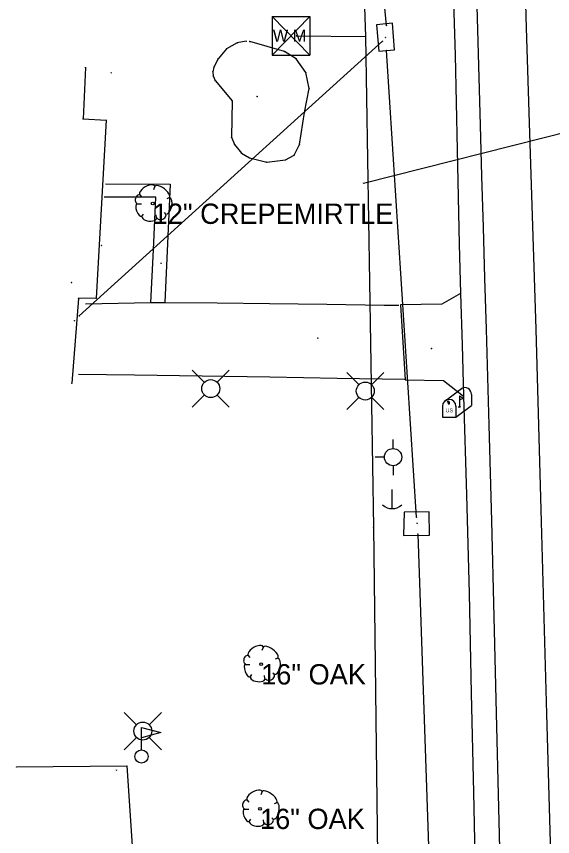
# Model space of a CAD drawing. Extents: x 1930288 to 1941089, y 588389 to 611475.
# Drawn here: x 1930752.1 to 1930884, y 597803.8 to 598005.7 of the extents above; entities that cross this region are included whole.
import ezdxf

# ---------------------------------------------------------------- set-up
doc = ezdxf.new("R2010")
doc.units = 0
for name, color, linetype in [('S_BUILDING', 7, 'Continuous'), ('S_DRG_PT_SYM', 7, 'Continuous'), ('S_DRIVEWAY', 7, 'Continuous'), ('S_DROP_INLET', 7, 'Continuous'), ('S_EDGE_PAVEMENT', 7, 'Continuous'), ('S_FLAG_POLE', 7, 'Continuous'), ('S_GRD_PT_SYM', 7, 'Continuous'), ('S_LANDSCAPING', 7, 'Continuous'), ('S_MAILBOX', 7, 'Continuous'), ('S_MSC_PT_SYM', 7, 'Continuous'), ('S_PAVEMENT_CROWN', 7, 'Continuous'), ('S_SANITARY_SEWER', 7, 'Continuous'), ('S_SHOULDER', 7, 'Continuous'), ('S_SIDEWALK', 7, 'Continuous'), ('S_STORM_SEWER', 7, 'Continuous'), ('S_STR_PT_SYM', 7, 'Continuous'), ('S_TREE', 7, 'Continuous'), ('S_TREE_ANNOT', 7, 'Continuous'), ('S_UTILITY_POLE', 7, 'Continuous'), ('S_UTL_PT_SYM', 7, 'Continuous'), ('S_WATER_UTILITIES', 7, 'Continuous')]:
    doc.layers.add(name, color=color, linetype=linetype)

msp = doc.modelspace()

# ---------------------------------------------------------------- linework, layer by layer
at = {"layer": 'S_BUILDING'}
for p, q in [((1930769.15, 597993.1), (1930768.55, 597980.46)), ((1930768.55, 597980.46), (1930774.22, 597980.17)), ((1930774.22, 597980.17), (1930771.74, 597936.32)), ((1930767.36, 597936.21), (1930765.74, 597915.38)), ((1930771.74, 597936.32), (1930767.36, 597936.21)), ((1930752.17, 597820.91), (1930779.32, 597821.17)), ((1930779.32, 597821.17), (1930780.88, 597796.72))]:
    msp.add_line(p, q, dxfattribs=at)
at = {"layer": 'S_DRG_PT_SYM'}
for points in [[(1930842.89, 598000.52), (1930842.89, 598000.57), (1930842.89, 598000.52), (1930842.84, 598000.52), (1930842.89, 598000.52), (1930842.89, 598000.47), (1930842.89, 598000.52), (1930842.94, 598000.52)], [(1930766.4, 597930.76), (1930766.4, 597930.81), (1930766.4, 597930.76), (1930766.35, 597930.76), (1930766.4, 597930.76), (1930766.4, 597930.71), (1930766.4, 597930.76), (1930766.45, 597930.76)], [(1930850.71, 597880.91), (1930850.71, 597880.96), (1930850.71, 597880.91), (1930850.66, 597880.91), (1930850.71, 597880.91), (1930850.71, 597880.86), (1930850.71, 597880.91), (1930850.76, 597880.91)]]:
    msp.add_lwpolyline(points, dxfattribs=at)
at = {"layer": 'S_DRIVEWAY'}
for points in [[(1930861.39, 597937.48), (1930856.83, 597934.8), (1930846.65, 597934.64), (1930847.76, 597916.23), (1930857.19, 597916.08), (1930862.15, 597912.21)], [(1930769.09, 597934.89), (1930785.23, 597935.26), (1930788.63, 597935.25), (1930801.52, 597935.14), (1930814.41, 597935.02), (1930828.49, 597934.8), (1930842.58, 597934.58), (1930846.18, 597934.58)], [(1930847.61, 597916.26), (1930831.06, 597916.56), (1930814.5, 597916.86), (1930797.85, 597917.11), (1930781.19, 597917.37), (1930767.38, 597917.52)]]:
    msp.add_lwpolyline(points, dxfattribs=at)
at = {"layer": 'S_DROP_INLET'}
for points in [[(1930840.69, 598003.64), (1930841.3, 597997.15), (1930845.17, 597997.43), (1930844.65, 598003.98)], [(1930844.65, 598003.98), (1930840.69, 598003.64)], [(1930847.51, 597883.66), (1930847.36, 597877.87), (1930853.74, 597877.95), (1930853.7, 597883.75)], [(1930853.7, 597883.75), (1930847.51, 597883.66)]]:
    msp.add_lwpolyline(points, dxfattribs=at)
at = {"layer": 'S_EDGE_PAVEMENT'}
msp.add_lwpolyline([(1930861.97, 598136.6), (1930862.32, 598122.16), (1930862.67, 598107.72), (1930863.02, 598093.28), (1930863.37, 598078.84), (1930863.8, 598061.3), (1930864.24, 598043.75), (1930864.93, 598025.92), (1930865.59, 598002.39), (1930866.24, 597978.87), (1930866.59, 597966.32), (1930866.95, 597953.76), (1930867.3, 597941.21), (1930867.66, 597928.66), (1930868.33, 597905.09), (1930869.01, 597881.53), (1930869.59, 597857.83), (1930870.18, 597834.13), (1930870.73, 597810.89), (1930871.29, 597787.65)], dxfattribs=at)
at = {"layer": 'S_FLAG_POLE'}
for p, q in [((1930782.9, 597825.12), (1930782.9, 597830.66)), ((1930782.9, 597830.66), (1930787.67, 597829.38)), ((1930787.67, 597829.38), (1930782.9, 597828.1))]:
    msp.add_line(p, q, dxfattribs=at)
msp.add_circle((1930782.9, 597823.49), 1.63, dxfattribs=at)
at = {"layer": 'S_GRD_PT_SYM'}
for points in [[(1930806.46, 597999.14), (1930806.46, 597999.19), (1930806.46, 597999.14), (1930806.41, 597999.14), (1930806.46, 597999.14), (1930806.46, 597999.09), (1930806.46, 597999.14), (1930806.51, 597999.14)], [(1930808.66, 597999.57), (1930808.66, 597999.62), (1930808.66, 597999.57), (1930808.61, 597999.57), (1930808.66, 597999.57), (1930808.66, 597999.52), (1930808.66, 597999.57), (1930808.71, 597999.57)], [(1930809.55, 597999.5), (1930809.55, 597999.55), (1930809.55, 597999.5), (1930809.5, 597999.5), (1930809.55, 597999.5), (1930809.55, 597999.45), (1930809.55, 597999.5), (1930809.6, 597999.5)], [(1930803.79, 597997.67), (1930803.79, 597997.72), (1930803.79, 597997.67), (1930803.74, 597997.67), (1930803.79, 597997.67), (1930803.79, 597997.62), (1930803.79, 597997.67), (1930803.84, 597997.67)], [(1930801.75, 597995.24), (1930801.75, 597995.29), (1930801.75, 597995.24), (1930801.7, 597995.24), (1930801.75, 597995.24), (1930801.75, 597995.19), (1930801.75, 597995.24), (1930801.8, 597995.24)], [(1930818.07, 597997.02), (1930818.07, 597997.07), (1930818.07, 597997.02), (1930818.02, 597997.02), (1930818.07, 597997.02), (1930818.07, 597996.97), (1930818.07, 597997.02), (1930818.12, 597997.02)], [(1930820.93, 597995.25), (1930820.93, 597995.3), (1930820.93, 597995.25), (1930820.88, 597995.25), (1930820.93, 597995.25), (1930820.93, 597995.2), (1930820.93, 597995.25), (1930820.98, 597995.25)], [(1930800.71, 597993.22), (1930800.71, 597993.27), (1930800.71, 597993.22), (1930800.66, 597993.22), (1930800.71, 597993.22), (1930800.71, 597993.17), (1930800.71, 597993.22), (1930800.76, 597993.22)], [(1930800.46, 597992.05), (1930800.46, 597992.1), (1930800.46, 597992.05), (1930800.41, 597992.05), (1930800.46, 597992.05), (1930800.46, 597992), (1930800.46, 597992.05), (1930800.51, 597992.05)], [(1930823.3, 597991.91), (1930823.3, 597991.96), (1930823.3, 597991.91), (1930823.25, 597991.91), (1930823.3, 597991.91), (1930823.3, 597991.86), (1930823.3, 597991.91), (1930823.35, 597991.91)], [(1930800.57, 597991.01), (1930800.57, 597991.06), (1930800.57, 597991.01), (1930800.52, 597991.01), (1930800.57, 597991.01), (1930800.57, 597990.96), (1930800.57, 597991.01), (1930800.62, 597991.01)], [(1930800.99, 597989.87), (1930800.99, 597989.92), (1930800.99, 597989.87), (1930800.94, 597989.87), (1930800.99, 597989.87), (1930800.99, 597989.82), (1930800.99, 597989.87), (1930801.04, 597989.87)], [(1930824.11, 597987.91), (1930824.11, 597987.96), (1930824.11, 597987.91), (1930824.06, 597987.91), (1930824.11, 597987.91), (1930824.11, 597987.86), (1930824.11, 597987.91), (1930824.16, 597987.91)], [(1930805.22, 597984.88), (1930805.22, 597984.93), (1930805.22, 597984.88), (1930805.17, 597984.88), (1930805.22, 597984.88), (1930805.22, 597984.83), (1930805.22, 597984.88), (1930805.27, 597984.88)], [(1930823.01, 597982.05), (1930823.01, 597982.1), (1930823.01, 597982.05), (1930822.96, 597982.05), (1930823.01, 597982.05), (1930823.01, 597982), (1930823.01, 597982.05), (1930823.06, 597982.05)], [(1930805.08, 597975.91), (1930805.08, 597975.96), (1930805.08, 597975.91), (1930805.03, 597975.91), (1930805.08, 597975.91), (1930805.08, 597975.86), (1930805.08, 597975.91), (1930805.13, 597975.91)], [(1930805.77, 597974.17), (1930805.77, 597974.22), (1930805.77, 597974.17), (1930805.72, 597974.17), (1930805.77, 597974.17), (1930805.77, 597974.12), (1930805.77, 597974.17), (1930805.82, 597974.17)], [(1930821.81, 597974.17), (1930821.81, 597974.22), (1930821.81, 597974.17), (1930821.76, 597974.17), (1930821.81, 597974.17), (1930821.81, 597974.12), (1930821.81, 597974.17), (1930821.86, 597974.17)], [(1930807.54, 597971.99), (1930807.54, 597972.04), (1930807.54, 597971.99), (1930807.49, 597971.99), (1930807.54, 597971.99), (1930807.54, 597971.94), (1930807.54, 597971.99), (1930807.59, 597971.99)], [(1930809.49, 597970.89), (1930809.49, 597970.94), (1930809.49, 597970.89), (1930809.44, 597970.89), (1930809.49, 597970.89), (1930809.49, 597970.84), (1930809.49, 597970.89), (1930809.54, 597970.89)], [(1930820.45, 597971.55), (1930820.45, 597971.6), (1930820.45, 597971.55), (1930820.4, 597971.55), (1930820.45, 597971.55), (1930820.45, 597971.5), (1930820.45, 597971.55), (1930820.5, 597971.55)], [(1930813.73, 597969.81), (1930813.73, 597969.86), (1930813.73, 597969.81), (1930813.68, 597969.81), (1930813.73, 597969.81), (1930813.73, 597969.76), (1930813.73, 597969.81), (1930813.78, 597969.81)], [(1930818.34, 597970.34), (1930818.34, 597970.39), (1930818.34, 597970.34), (1930818.29, 597970.34), (1930818.34, 597970.34), (1930818.34, 597970.29), (1930818.34, 597970.34), (1930818.39, 597970.34)]]:
    msp.add_lwpolyline(points, dxfattribs=at)
at = {"layer": 'S_LANDSCAPING'}
for p, q in [((1930806.46, 597999.14), (1930803.79, 597997.67)), ((1930808.66, 597999.57), (1930806.46, 597999.14)), ((1930818.07, 597997.02), (1930809.55, 597999.5)), ((1930803.79, 597997.67), (1930801.75, 597995.24)), ((1930801.75, 597995.24), (1930800.71, 597993.22)), ((1930820.93, 597995.25), (1930818.07, 597997.02)), ((1930823.3, 597991.91), (1930820.93, 597995.25)), ((1930800.71, 597993.22), (1930800.46, 597992.05)), ((1930800.46, 597992.05), (1930800.57, 597991.01)), ((1930824.11, 597987.91), (1930823.3, 597991.91)), ((1930800.57, 597991.01), (1930800.99, 597989.87)), ((1930800.99, 597989.87), (1930805.22, 597984.88)), ((1930823.01, 597982.05), (1930824.11, 597987.91)), ((1930805.22, 597984.88), (1930805.08, 597975.91)), ((1930821.81, 597974.17), (1930823.01, 597982.05)), ((1930805.08, 597975.91), (1930805.77, 597974.17)), ((1930805.77, 597974.17), (1930807.54, 597971.99)), ((1930820.45, 597971.55), (1930821.81, 597974.17)), ((1930807.54, 597971.99), (1930809.49, 597970.89)), ((1930809.49, 597970.89), (1930813.73, 597969.81)), ((1930818.34, 597970.34), (1930820.45, 597971.55)), ((1930813.73, 597969.81), (1930818.34, 597970.34))]:
    msp.add_line(p, q, dxfattribs=at)
at = {"layer": 'S_MAILBOX'}
for p, q in [((1930857.49, 597911), (1930861.62, 597914.11)), ((1930864.06, 597912.64), (1930864.06, 597909.92)), ((1930861.11, 597912.29), (1930861.11, 597909.58)), ((1930856.94, 597909.73), (1930856.94, 597907.01)), ((1930860.26, 597907.01), (1930864.06, 597909.92)), ((1930860.26, 597909.73), (1930860.26, 597907.01)), ((1930856.94, 597907.01), (1930860.26, 597907.01))]:
    msp.add_line(p, q, dxfattribs=at)
for points in [[(1930858.12, 597910.84), (1930858.34, 597910.71), (1930858.34, 597910.32), (1930858.65, 597910.32), (1930858.65, 597910.68), (1930858.45, 597910.93), (1930858.12, 597910.87)], [(1930861.11, 597912.29), (1930862.21, 597911.63), (1930861.11, 597911.28)]]:
    msp.add_lwpolyline(points, dxfattribs=at)
for centre, end in [((1930862.39, 597912.64), 117.5718), ((1930858.6, 597909.73), 180)]:
    msp.add_arc(centre, 1.66, 0, end, dxfattribs=at)
msp.add_ellipse((1930861.11, 597909.58), major_axis=(0.145, 0.132), ratio=0.564646, dxfattribs=at)
at = {"layer": 'S_MSC_PT_SYM'}
for points in [[(1930843.2, 598003.4), (1930843.2, 598003.45), (1930843.2, 598003.4), (1930843.15, 598003.4), (1930843.2, 598003.4), (1930843.2, 598003.35), (1930843.2, 598003.4), (1930843.25, 598003.4)], [(1930842.16, 597999.56), (1930842.16, 597999.61), (1930842.16, 597999.56), (1930842.1, 597999.56), (1930842.16, 597999.56), (1930842.16, 597999.51), (1930842.16, 597999.56), (1930842.21, 597999.56)], [(1930843.15, 597997.3), (1930843.15, 597997.35), (1930843.15, 597997.3), (1930843.1, 597997.3), (1930843.15, 597997.3), (1930843.15, 597997.25), (1930843.15, 597997.3), (1930843.2, 597997.3)], [(1930775.45, 597991.8), (1930775.45, 597991.85), (1930775.45, 597991.8), (1930775.4, 597991.8), (1930775.45, 597991.8), (1930775.45, 597991.75), (1930775.45, 597991.8), (1930775.5, 597991.8)], [(1930811.36, 597985.96), (1930811.36, 597986.01), (1930811.36, 597985.96), (1930811.31, 597985.96), (1930811.36, 597985.96), (1930811.36, 597985.91), (1930811.36, 597985.96), (1930811.41, 597985.96)], [(1930773.03, 597949.32), (1930773.03, 597949.37), (1930773.03, 597949.32), (1930772.98, 597949.32), (1930773.03, 597949.32), (1930773.03, 597949.27), (1930773.03, 597949.32), (1930773.08, 597949.32)], [(1930787.72, 597944.92), (1930787.72, 597944.97), (1930787.72, 597944.92), (1930787.67, 597944.92), (1930787.72, 597944.92), (1930787.72, 597944.87), (1930787.72, 597944.92), (1930787.77, 597944.92)], [(1930765.68, 597940.16), (1930765.68, 597940.21), (1930765.68, 597940.16), (1930765.63, 597940.16), (1930765.68, 597940.16), (1930765.68, 597940.11), (1930765.68, 597940.16), (1930765.73, 597940.16)], [(1930767.59, 597931.96), (1930767.59, 597932.01), (1930767.59, 597931.96), (1930767.54, 597931.96), (1930767.59, 597931.96), (1930767.59, 597931.91), (1930767.59, 597931.96), (1930767.64, 597931.96)], [(1930826.28, 597926.51), (1930826.28, 597926.56), (1930826.28, 597926.51), (1930826.23, 597926.51), (1930826.28, 597926.51), (1930826.28, 597926.46), (1930826.28, 597926.51), (1930826.33, 597926.51)], [(1930854.24, 597923.93), (1930854.24, 597923.98), (1930854.24, 597923.93), (1930854.19, 597923.93), (1930854.24, 597923.93), (1930854.24, 597923.88), (1930854.24, 597923.93), (1930854.29, 597923.93)], [(1930850.52, 597882.37), (1930850.52, 597882.42), (1930850.52, 597882.37), (1930850.47, 597882.37), (1930850.52, 597882.37), (1930850.52, 597882.32), (1930850.52, 597882.37), (1930850.57, 597882.37)], [(1930850.87, 597878.26), (1930850.87, 597878.31), (1930850.87, 597878.26), (1930850.82, 597878.26), (1930850.87, 597878.26), (1930850.87, 597878.21), (1930850.87, 597878.26), (1930850.92, 597878.26)], [(1930776.77, 597820.14), (1930776.77, 597820.19), (1930776.77, 597820.14), (1930776.72, 597820.14), (1930776.77, 597820.14), (1930776.77, 597820.09), (1930776.77, 597820.14), (1930776.82, 597820.14)]]:
    msp.add_lwpolyline(points, dxfattribs=at)
at = {"layer": 'S_PAVEMENT_CROWN'}
msp.add_lwpolyline([(1930874.52, 598135.93), (1930874.85, 598121.34), (1930875.18, 598106.75), (1930875.51, 598092.15), (1930875.84, 598077.56), (1930876.1, 598064.74), (1930876.35, 598051.91), (1930876.61, 598039.09), (1930876.86, 598026.27), (1930877.56, 598002.85), (1930878.25, 597979.44), (1930878.66, 597966.75), (1930879.07, 597954.07), (1930879.48, 597941.38), (1930879.89, 597928.7), (1930880.57, 597904.97), (1930881.24, 597881.25), (1930881.88, 597857.6), (1930882.52, 597833.95), (1930883.18, 597810.9), (1930883.85, 597787.85)], dxfattribs=at)
at = {"layer": 'S_SANITARY_SEWER'}
msp.add_line((1930837.54, 597964.65), (1930896.27, 597979.53), dxfattribs=at)
at = {"layer": 'S_SHOULDER'}
msp.add_lwpolyline([(1930861.97, 598136.6), (1930856.85, 598136.29), (1930857.08, 598121.84), (1930857.31, 598107.38), (1930857.54, 598092.92), (1930857.77, 598078.47), (1930858.08, 598061.18), (1930858.39, 598043.88), (1930859.23, 598022.21), (1930859.65, 598009.16), (1930860.08, 597996.1), (1930860.58, 597972.84), (1930861.09, 597949.57), (1930861.39, 597937.48), (1930861.77, 597924.84), (1930862.15, 597912.21), (1930862.82, 597887.9), (1930863.5, 597863.59), (1930864.03, 597839.11), (1930864.57, 597814.62), (1930865.11, 597791.12)], dxfattribs=at)
at = {"layer": 'S_SIDEWALK'}
for points in [[(1930774.01, 597964.5), (1930789.91, 597964.38), (1930789.27, 597949.81), (1930788.63, 597935.25)], [(1930785.23, 597935.26), (1930785.83, 597948.2), (1930786.43, 597961.14), (1930773.7, 597961.19)]]:
    msp.add_lwpolyline(points, dxfattribs=at)
at = {"layer": 'S_STORM_SEWER'}
for p, q in [((1930843.2, 598003.4), (1930828.55, 598152.44)), ((1930842.16, 597999.56), (1930767.59, 597931.96)), ((1930850.52, 597882.37), (1930843.15, 597997.3)), ((1930850.87, 597878.26), (1930854.28, 597778.44))]:
    msp.add_line(p, q, dxfattribs=at)
at = {"layer": 'S_STR_PT_SYM'}
for points in [[(1930769.15, 597993.1), (1930769.15, 597993.15), (1930769.15, 597993.1), (1930769.1, 597993.1), (1930769.15, 597993.1), (1930769.15, 597993.05), (1930769.15, 597993.1), (1930769.2, 597993.1)], [(1930768.55, 597980.46), (1930768.55, 597980.51), (1930768.55, 597980.46), (1930768.5, 597980.46), (1930768.55, 597980.46), (1930768.55, 597980.41), (1930768.55, 597980.46), (1930768.6, 597980.46)], [(1930774.22, 597980.17), (1930774.22, 597980.22), (1930774.22, 597980.17), (1930774.17, 597980.17), (1930774.22, 597980.17), (1930774.22, 597980.12), (1930774.22, 597980.17), (1930774.27, 597980.17)], [(1930767.36, 597936.21), (1930767.36, 597936.26), (1930767.36, 597936.21), (1930767.31, 597936.21), (1930767.36, 597936.21), (1930767.36, 597936.16), (1930767.36, 597936.21), (1930767.41, 597936.21)], [(1930771.74, 597936.32), (1930771.74, 597936.37), (1930771.74, 597936.32), (1930771.69, 597936.32), (1930771.74, 597936.32), (1930771.74, 597936.27), (1930771.74, 597936.32), (1930771.79, 597936.32)], [(1930765.74, 597915.38), (1930765.74, 597915.43), (1930765.74, 597915.38), (1930765.69, 597915.38), (1930765.74, 597915.38), (1930765.74, 597915.33), (1930765.74, 597915.38), (1930765.79, 597915.38)], [(1930752.17, 597820.91), (1930752.17, 597820.96), (1930752.17, 597820.91), (1930752.12, 597820.91), (1930752.17, 597820.91), (1930752.17, 597820.86), (1930752.17, 597820.91), (1930752.22, 597820.91)], [(1930779.32, 597821.17), (1930779.32, 597821.22), (1930779.32, 597821.17), (1930779.27, 597821.17), (1930779.32, 597821.17), (1930779.32, 597821.12), (1930779.32, 597821.17), (1930779.37, 597821.17)]]:
    msp.add_lwpolyline(points, dxfattribs=at)
at = {"layer": 'S_TREE'}
for p, q in [((1930786.21, 597963.85), (1930785.82, 597963)), ((1930782.41, 597961.83), (1930782.91, 597961.25)), ((1930789.77, 597961.06), (1930789.11, 597960.79)), ((1930781.75, 597959.51), (1930782.87, 597959.51)), ((1930782.91, 597956.33), (1930783.38, 597957.03)), ((1930786.59, 597956.06), (1930786.52, 597956.84)), ((1930789, 597956.95), (1930788.53, 597957.38)), ((1930812.89, 597850.47), (1930812.5, 597849.62)), ((1930809.09, 597848.45), (1930809.59, 597847.87)), ((1930808.43, 597846.13), (1930809.55, 597846.13)), ((1930816.45, 597847.68), (1930815.79, 597847.41)), ((1930815.68, 597843.57), (1930815.21, 597844)), ((1930809.59, 597842.95), (1930810.06, 597843.65)), ((1930813.27, 597842.68), (1930813.2, 597843.45)), ((1930812.61, 597814.87), (1930812.22, 597814.02)), ((1930808.81, 597812.86), (1930809.31, 597812.28)), ((1930816.17, 597812.08), (1930815.51, 597811.81)), ((1930808.15, 597810.53), (1930809.27, 597810.53)), ((1930809.31, 597807.36), (1930809.78, 597808.05)), ((1930812.99, 597807.09), (1930812.92, 597807.86)), ((1930815.4, 597807.98), (1930814.93, 597808.4))]:
    msp.add_line(p, q, dxfattribs=at)
for centre in [(1930785.65, 597959.6), (1930812.33, 597846.22), (1930812.05, 597810.63)]:
    msp.add_circle(centre, 0.341, dxfattribs=at)
for centre, major_axis, ratio, start_param, end_param in [((1930784.31, 597962.81), (1.86, 1.08), 0.471018, 0, 3.141593), ((1930787.97, 597962.48), (-1.81, 1.36), 0.405113, 3.141593, 6.283186), ((1930782.08, 597960.69), (0.31, 1.03), 0.646762, 0, 3.141593), ((1930789.32, 597959.07), (0.46, 2.04), 0.482994, 3.141593, 6.283185), ((1930782.38, 597958.04), (-0.61, 1.6), 0.420543, 6.283185, 9.424777), ((1930787.8, 597956.55), (1.09, 0.46), 0.711534, 3.141592, 6.283185), ((1930784.84, 597956.26), (-1.83, 0.19), 0.529943, 0, 3.141593), ((1930810.99, 597849.43), (1.86, 1.08), 0.471018, 0, 3.141593), ((1930814.65, 597849.1), (-1.81, 1.36), 0.405113, 3.141593, 6.283186), ((1930808.76, 597847.31), (0.31, 1.03), 0.646762, 0, 3.141593), ((1930816, 597845.69), (0.46, 2.04), 0.482994, 3.141593, 6.283185), ((1930809.06, 597844.66), (-0.61, 1.6), 0.420543, 6.283185, 9.424777), ((1930811.52, 597842.88), (-1.83, 0.19), 0.529943, 0, 3.141593), ((1930814.48, 597843.17), (1.09, 0.46), 0.711534, 3.141592, 6.283185), ((1930810.71, 597813.83), (1.86, 1.08), 0.471018, 0, 3.141593), ((1930814.37, 597813.51), (-1.81, 1.36), 0.405113, 3.141593, 6.283186), ((1930808.48, 597811.72), (0.31, 1.03), 0.646762, 0, 3.141593), ((1930815.72, 597810.1), (0.46, 2.04), 0.482994, 3.141593, 6.283185), ((1930808.78, 597809.07), (-0.61, 1.6), 0.420543, 6.283185, 9.424777), ((1930811.24, 597807.29), (-1.83, 0.19), 0.529943, 0, 3.141593), ((1930814.2, 597807.58), (1.09, 0.46), 0.711534, 3.141592, 6.283185)]:
    msp.add_ellipse(centre, major_axis=major_axis, ratio=ratio, start_param=start_param, end_param=end_param, dxfattribs=at)
at = {"layer": 'S_UTILITY_POLE'}
for p, q in [((1930798.34, 597915.63), (1930795.35, 597918.61)), ((1930801.51, 597915.63), (1930804.5, 597918.61)), ((1930836.36, 597915.03), (1930833.38, 597918.01)), ((1930839.54, 597915.03), (1930842.53, 597918.01)), ((1930798.34, 597912.45), (1930795.35, 597909.47)), ((1930801.51, 597912.45), (1930804.5, 597909.47)), ((1930836.36, 597911.85), (1930833.38, 597908.87)), ((1930839.54, 597911.85), (1930842.53, 597908.87)), ((1930844.8, 597899.29), (1930844.8, 597901.54)), ((1930842.71, 597897.16), (1930840.38, 597897.16)), ((1930844.88, 597892.74), (1930844.88, 597895.06)), ((1930844.51, 597889.21), (1930844.51, 597884.48)), ((1930781.63, 597831.32), (1930778.64, 597834.31)), ((1930784.8, 597831.32), (1930787.79, 597834.31)), ((1930781.63, 597828.15), (1930778.64, 597825.16)), ((1930784.8, 597828.15), (1930787.79, 597825.16))]:
    msp.add_line(p, q, dxfattribs=at)
for centre, radius in [((1930799.93, 597914.05), 2.21), ((1930837.96, 597913.45), 2.21), ((1930844.8, 597897.18), 2.13), ((1930783.22, 597829.74), 2.21)]:
    msp.add_circle(centre, radius, dxfattribs=at)
msp.add_arc((1930844.58, 597887.91), 3.41, 226.3972, 313.6028, dxfattribs=at)
at = {"layer": 'S_UTL_PT_SYM'}
for points in [[(1930843.2, 598003.4), (1930843.2, 598003.45), (1930843.2, 598003.4), (1930843.15, 598003.4), (1930843.2, 598003.4), (1930843.2, 598003.35), (1930843.2, 598003.4), (1930843.25, 598003.4)], [(1930821.04, 598000.86), (1930821.04, 598000.91), (1930821.04, 598000.86), (1930820.99, 598000.86), (1930821.04, 598000.86), (1930821.04, 598000.81), (1930821.04, 598000.86), (1930821.09, 598000.86)], [(1930837.98, 598000.7), (1930837.98, 598000.75), (1930837.98, 598000.7), (1930837.93, 598000.7), (1930837.98, 598000.7), (1930837.98, 598000.65), (1930837.98, 598000.7), (1930838.03, 598000.7)], [(1930837.98, 598000.7), (1930837.98, 598000.75), (1930837.98, 598000.7), (1930837.93, 598000.7), (1930837.98, 598000.7), (1930837.98, 598000.65), (1930837.98, 598000.7), (1930838.03, 598000.7)], [(1930842.16, 597999.56), (1930842.16, 597999.61), (1930842.16, 597999.56), (1930842.1, 597999.56), (1930842.16, 597999.56), (1930842.16, 597999.51), (1930842.16, 597999.56), (1930842.21, 597999.56)], [(1930842.89, 598000.52), (1930842.89, 598000.57), (1930842.89, 598000.52), (1930842.84, 598000.52), (1930842.89, 598000.52), (1930842.89, 598000.47), (1930842.89, 598000.52), (1930842.94, 598000.52)], [(1930843.15, 597997.3), (1930843.15, 597997.35), (1930843.15, 597997.3), (1930843.1, 597997.3), (1930843.15, 597997.3), (1930843.15, 597997.25), (1930843.15, 597997.3), (1930843.2, 597997.3)], [(1930837.54, 597964.65), (1930837.54, 597964.7), (1930837.54, 597964.65), (1930837.49, 597964.65), (1930837.54, 597964.65), (1930837.54, 597964.6), (1930837.54, 597964.65), (1930837.59, 597964.65)], [(1930766.4, 597930.76), (1930766.4, 597930.81), (1930766.4, 597930.76), (1930766.35, 597930.76), (1930766.4, 597930.76), (1930766.4, 597930.71), (1930766.4, 597930.76), (1930766.45, 597930.76)], [(1930767.59, 597931.96), (1930767.59, 597932.01), (1930767.59, 597931.96), (1930767.54, 597931.96), (1930767.59, 597931.96), (1930767.59, 597931.91), (1930767.59, 597931.96), (1930767.64, 597931.96)], [(1930850.52, 597882.37), (1930850.52, 597882.42), (1930850.52, 597882.37), (1930850.47, 597882.37), (1930850.52, 597882.37), (1930850.52, 597882.32), (1930850.52, 597882.37), (1930850.57, 597882.37)], [(1930850.71, 597880.91), (1930850.71, 597880.96), (1930850.71, 597880.91), (1930850.66, 597880.91), (1930850.71, 597880.91), (1930850.71, 597880.86), (1930850.71, 597880.91), (1930850.76, 597880.91)], [(1930839.97, 597879.92), (1930839.97, 597879.97), (1930839.97, 597879.92), (1930839.92, 597879.92), (1930839.97, 597879.92), (1930839.97, 597879.87), (1930839.97, 597879.92), (1930840.02, 597879.92)], [(1930850.87, 597878.26), (1930850.87, 597878.31), (1930850.87, 597878.26), (1930850.82, 597878.26), (1930850.87, 597878.26), (1930850.87, 597878.21), (1930850.87, 597878.26), (1930850.92, 597878.26)]]:
    msp.add_lwpolyline(points, dxfattribs=at)
at = {"layer": 'S_WATER_UTILITIES'}
for p, q in [((1930831.37, 598238.21), (1930837.98, 598000.7)), ((1930815.01, 598005.67), (1930824.35, 598005.67)), ((1930815.01, 598005.67), (1930815.01, 597996.17)), ((1930815.01, 598005.67), (1930824.35, 597996.17)), ((1930824.35, 598005.67), (1930815.01, 597996.17)), ((1930824.35, 598005.67), (1930824.35, 597996.17)), ((1930821.04, 598000.86), (1930837.98, 598000.7)), ((1930837.98, 598000.7), (1930839.97, 597879.92)), ((1930815.01, 597996.17), (1930824.35, 597996.17)), ((1930839.97, 597879.92), (1930841.28, 597769.64))]:
    msp.add_line(p, q, dxfattribs=at)

# ---------------------------------------------------------------- texts
at = {"layer": 'S_MAILBOX'}
msp.add_text('US', height=0.96, rotation=360, dxfattribs=at).set_placement((1930857.7, 597908.21))
at = {"layer": 'S_TREE_ANNOT'}
for s, p in [('12" CREPEMIRTLE', (1930785.65, 597954.6)), ('16" OAK', (1930812.33, 597841.22)), ('16" OAK', (1930812.05, 597805.63))]:
    msp.add_text(s, height=5, dxfattribs=at).set_placement(p)
at = {"layer": 'S_WATER_UTILITIES'}
msp.add_text('W M', height=3, rotation=360, dxfattribs=at).set_placement((1930815.21, 597999.43))

doc.saveas('drawing.dxf')
